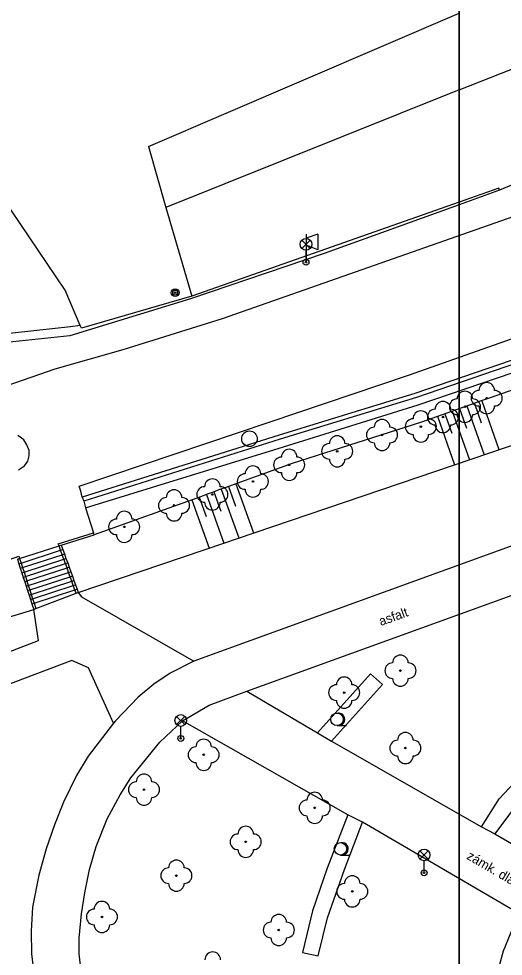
# Model space of a CAD drawing. Extents: x -493753 to -49290, y -1127285 to -112654.
# Drawn here: x -493153.3 to -493122.2, y -1126683.6 to -1126623.4 of the extents above; entities that cross this region are included whole.
import ezdxf

# ---------------------------------------------------------------- set-up
doc = ezdxf.new("R2010")
doc.units = 0
for name, color, linetype in [('Vrstva 10', 7, 'Continuous'), ('Vrstva 11', 7, 'Continuous'), ('Vrstva 14', 7, 'Continuous'), ('Vrstva 15', 7, 'Continuous'), ('Vrstva 21', 7, 'Continuous'), ('Vrstva 22', 7, 'Continuous'), ('Vrstva 23', 7, 'Continuous'), ('Vrstva 25', 7, 'Continuous'), ('Vrstva 27', 7, 'Continuous'), ('Vrstva 33', 7, 'Continuous'), ('Vrstva 36', 7, 'Continuous'), ('Vrstva 40', 7, 'Continuous'), ('Vrstva 60', 7, 'Continuous'), ('Vrstva 7', 7, 'Continuous'), ('Vrstva 8', 7, 'Continuous'), ('Vrstva 9', 7, 'Continuous')]:
    doc.layers.add(name, color=color, linetype=linetype)

msp = doc.modelspace()

# ---------------------------------------------------------------- linework, layer by layer
at = {"layer": 'Vrstva 10'}
for p, q in [((-493082.44, -1126643.04), (-493142.03, -1126664.63)), ((-493152.93, -1126650.43), (-493153.31, -1126650.14)), ((-493152.75, -1126650.75), (-493152.93, -1126650.43)), ((-493152.6, -1126651.1), (-493152.75, -1126650.75)), ((-493152.6, -1126651.46), (-493152.6, -1126651.1)), ((-493152.68, -1126651.8), (-493152.6, -1126651.46)), ((-493153.27, -1126652.35), (-493152.9, -1126652.09)), ((-493152.9, -1126652.09), (-493152.68, -1126651.8)), ((-493150.53, -1126657.19), (-493148.41, -1126656.53))]:
    msp.add_line(p, q, dxfattribs=at)
for points in [[(-493112.94, -1126633.09), (-493140.21, -1126642.65), (-493146.57, -1126644.64), (-493150.94, -1126645.89), (-493157.69, -1126648.21), (-493160.43, -1126649.13), (-493160.67, -1126649.21), (-493174.89, -1126654.03), (-493197.62, -1126661.66)], [(-493090.15, -1126633.48), (-493092.4, -1126634.08), (-493099.93, -1126637.44), (-493110.38, -1126641.71), (-493117.7, -1126644.26), (-493127.72, -1126647.7), (-493136.47, -1126650.38), (-493149.09, -1126654.35)], [(-493149.09, -1126654.35), (-493148.97, -1126654.78), (-493148.46, -1126656.39)], [(-493148.41, -1126656.53), (-493148.46, -1126656.39)], [(-493150.53, -1126657.19), (-493150.43, -1126657.47), (-493150.33, -1126657.75), (-493150.23, -1126658.04), (-493150.12, -1126658.32), (-493150.02, -1126658.6), (-493149.92, -1126658.89), (-493149.82, -1126659.17), (-493149.72, -1126659.45), (-493149.62, -1126659.73), (-493149.51, -1126660.01), (-493149.44, -1126660.22)], [(-493138.62, -1126666.56), (-493112.91, -1126657.25)], [(-493153.35, -1126658.08), (-493153.25, -1126658.39), (-493153.16, -1126658.67), (-493153.06, -1126658.96), (-493152.97, -1126659.25), (-493152.88, -1126659.53), (-493152.79, -1126659.82), (-493152.69, -1126660.1), (-493152.6, -1126660.39), (-493152.51, -1126660.67), (-493152.42, -1126660.96), (-493152.3, -1126661.31)], [(-493149.44, -1126660.22), (-493149.23, -1126660.5), (-493142.03, -1126664.63)], [(-493161.82, -1126667.07), (-493152, -1126663.31), (-493152.3, -1126661.31)], [(-493147.17, -1126668.61), (-493148.78, -1126665.07), (-493149.85, -1126664.59), (-493159.66, -1126668.3), (-493160.04, -1126668.71), (-493160.26, -1126669.2), (-493160.35, -1126669.68), (-493160.32, -1126670.13), (-493151.92, -1126688.64), (-493151.32, -1126688.27)], [(-493138.62, -1126666.56), (-493134.08, -1126669.23)], [(-493147.17, -1126668.61), (-493148.81, -1126670.73), (-493149.55, -1126671.97), (-493150.38, -1126673.68), (-493150.96, -1126675.13), (-493151.51, -1126676.67), (-493151.97, -1126678.38), (-493152.37, -1126680.43), (-493152.47, -1126681.97), (-493152.44, -1126683.41), (-493152.26, -1126684.82), (-493152.04, -1126685.92), (-493151.32, -1126688.27)], [(-493149.25, -1126684.51), (-493149.38, -1126683.42), (-493149.39, -1126682.42), (-493149.23, -1126680.86), (-493149.01, -1126679.5), (-493148.71, -1126678.01), (-493148.29, -1126676.52), (-493147.59, -1126674.75), (-493146.75, -1126673.21), (-493146.07, -1126672.12), (-493144.21, -1126669.84), (-493142.74, -1126668.47)], [(-493132.14, -1126674.49), (-493142.74, -1126668.47)], [(-493134.08, -1126669.23), (-493133.19, -1126669.76)], [(-493133.19, -1126669.76), (-493123.56, -1126675.27)], [(-493131.19, -1126674.97), (-493132.14, -1126674.49)], [(-493121.17, -1126680.84), (-493131.19, -1126674.97)], [(-493123.56, -1126675.27), (-493122.71, -1126675.72)], [(-493122.71, -1126675.72), (-493117.72, -1126678.6)]]:
    msp.add_lwpolyline(points, dxfattribs=at)
at = {"layer": 'Vrstva 11'}
msp.add_line((-493144.94, -1126631.6), (-493125, -1126623.04), dxfattribs=at)
for points in [[(-493125, -1126627.95), (-493116.83, -1126624.74)], [(-493125, -1126627.95), (-493143.81, -1126635.5)], [(-493149.18, -1126654.1), (-493149.28, -1126653.72), (-493149.38, -1126653.4), (-493137.19, -1126649.29), (-493128.18, -1126646.24), (-493118.42, -1126642.8), (-493110.87, -1126640.09), (-493100.4, -1126636.25), (-493092.65, -1126633.27), (-493092.49, -1126633.69)], [(-493092.49, -1126633.69), (-493099.98, -1126637.24), (-493110.5, -1126641.46), (-493117.77, -1126644.01), (-493127.83, -1126647.45), (-493136.55, -1126650.13), (-493149.18, -1126654.1), (-493149.09, -1126654.35)], [(-493153.35, -1126658.08), (-493153.21, -1126658.04), (-493150.67, -1126657.23), (-493150.53, -1126657.19)], [(-493153.25, -1126658.39), (-493153.11, -1126658.35), (-493150.57, -1126657.51), (-493150.43, -1126657.47)], [(-493153.16, -1126658.67), (-493153.02, -1126658.62), (-493150.47, -1126657.8), (-493150.33, -1126657.75)], [(-493153.06, -1126658.96), (-493152.92, -1126658.92), (-493150.36, -1126658.09), (-493150.23, -1126658.04)], [(-493152.97, -1126659.25), (-493152.83, -1126659.2), (-493150.26, -1126658.37), (-493150.12, -1126658.32)], [(-493152.88, -1126659.53), (-493152.74, -1126659.48), (-493150.16, -1126658.65), (-493150.02, -1126658.6)], [(-493152.79, -1126659.82), (-493152.65, -1126659.77), (-493150.06, -1126658.94), (-493149.92, -1126658.89)], [(-493152.69, -1126660.1), (-493152.55, -1126660.05), (-493149.96, -1126659.22), (-493149.82, -1126659.17)], [(-493152.6, -1126660.39), (-493152.46, -1126660.35), (-493149.86, -1126659.49), (-493149.72, -1126659.45)], [(-493152.51, -1126660.67), (-493152.37, -1126660.62), (-493149.76, -1126659.78), (-493149.62, -1126659.73)], [(-493152.42, -1126660.96), (-493152.27, -1126660.91), (-493149.66, -1126660.06), (-493149.51, -1126660.01)], [(-493152.3, -1126661.31), (-493152.16, -1126661.26), (-493149.58, -1126660.27), (-493149.44, -1126660.22)], [(-493142.03, -1126664.63), (-493143.55, -1126665.41), (-493144.58, -1126666.11), (-493145.6, -1126666.94), (-493147.06, -1126668.46), (-493147.17, -1126668.61)], [(-493142.74, -1126668.47), (-493141.03, -1126667.45), (-493138.62, -1126666.56)]]:
    msp.add_lwpolyline(points, dxfattribs=at)
at = {"layer": 'Vrstva 14'}
for points in [[(-493149.44, -1126660.22), (-493140.03, -1126657.04), (-493139.28, -1126656.77), (-493123.03, -1126651.26), (-493122.28, -1126650.99), (-493111.39, -1126647.34), (-493110.63, -1126647.08), (-493100.45, -1126643.64), (-493095.29, -1126641.22), (-493094.56, -1126640.89), (-493080.63, -1126634.46), (-493079.9, -1126634.13), (-493077.86, -1126633.18)], [(-493148.97, -1126654.78), (-493136.27, -1126650.87), (-493127.63, -1126648.17), (-493117.51, -1126644.74), (-493110.16, -1126642.18), (-493099.61, -1126637.87), (-493092.16, -1126634.52), (-493089.97, -1126633.86), (-493090.15, -1126633.48)], [(-493112.97, -1126644.2), (-493123, -1126647.73), (-493123.38, -1126647.86), (-493123.76, -1126647.99), (-493124.14, -1126648.13), (-493124.51, -1126648.26), (-493127.41, -1126649.28), (-493135.72, -1126651.95), (-493140.03, -1126653.51), (-493140.41, -1126653.64), (-493140.79, -1126653.78), (-493141.16, -1126653.91), (-493141.54, -1126654.05), (-493148.41, -1126656.53)], [(-493186.94, -1126669.58), (-493183.37, -1126670.76), (-493152.3, -1126661.31)]]:
    msp.add_lwpolyline(points, dxfattribs=at)
at = {"layer": 'Vrstva 15'}
for p, q in [((-493124.01, -1126648.08), (-493123.57, -1126649.34)), ((-493123.54, -1126647.92), (-493122.44, -1126651.05)), ((-493125.9, -1126648.75), (-493125.46, -1126649.99)), ((-493125.43, -1126648.58), (-493124.33, -1126651.7)), ((-493124.96, -1126648.42), (-493124.52, -1126649.67)), ((-493124.49, -1126648.25), (-493123.38, -1126651.38)), ((-493126.37, -1126648.91), (-493125.28, -1126652.02)), ((-493139.8, -1126653.42), (-493139.34, -1126654.68)), ((-493139.33, -1126653.25), (-493138.19, -1126656.4)), ((-493141.68, -1126654.1), (-493141.23, -1126655.35)), ((-493141.21, -1126653.93), (-493140.09, -1126657.06)), ((-493140.74, -1126653.76), (-493140.29, -1126655.01)), ((-493140.27, -1126653.59), (-493139.14, -1126656.72)), ((-493142.15, -1126654.27), (-493141.03, -1126657.37))]:
    msp.add_line(p, q, dxfattribs=at)
at = {"layer": 'Vrstva 21'}
for p, q in [((-493122.42, -1126673.46), (-493120.22, -1126671.1)), ((-493120.94, -1126673.37), (-493122.71, -1126675.72)), ((-493123.56, -1126675.27), (-493122.42, -1126673.46)), ((-493132.14, -1126674.49), (-493133.47, -1126677.92)), ((-493132.35, -1126678.01), (-493131.19, -1126674.97)), ((-493133.47, -1126677.92), (-493134.41, -1126680.65)), ((-493133.44, -1126681.1), (-493132.35, -1126678.01)), ((-493134.41, -1126680.65), (-493135.05, -1126683.34)), ((-493134.04, -1126683.55), (-493133.44, -1126681.1)), ((-493135.05, -1126683.34), (-493134.04, -1126683.55))]:
    msp.add_line(p, q, dxfattribs=at)
msp.add_lwpolyline([(-493122.1, -1126690.56), (-493123.14, -1126690.53), (-493123.05, -1126687.84), (-493122.66, -1126685.11), (-493122.14, -1126683.22), (-493121.17, -1126680.84)], dxfattribs=at)
at = {"layer": 'Vrstva 22'}
for centre in [(-493123.22, -1126647.75), (-493124.62, -1126648.3), (-493126.03, -1126648.96), (-493127.45, -1126649.57), (-493129.94, -1126650.11), (-493132.82, -1126651.16), (-493135.9, -1126652.03), (-493138.23, -1126653.1), (-493140.83, -1126653.93), (-493143.29, -1126654.63), (-493146.49, -1126656.01), (-493128.76, -1126665.24), (-493132.37, -1126666.65), (-493128.44, -1126670.21), (-493141.39, -1126670.64), (-493145.22, -1126672.88), (-493134.26, -1126674.05), (-493138.69, -1126676.23), (-493143.14, -1126678.4), (-493131.85, -1126679.41), (-493147.92, -1126681.05), (-493136.57, -1126681.89)]:
    msp.add_circle(centre, 0.05, dxfattribs=at)
for centre, start, end in [((-493123.22, -1126647.25), 360, 180), ((-493124.62, -1126647.8), 360, 180), ((-493123.72, -1126647.75), 90, 270), ((-493122.72, -1126647.75), 270, 90), ((-493126.03, -1126648.46), 360, 180), ((-493125.12, -1126648.3), 90, 270), ((-493124.12, -1126648.3), 270, 90), ((-493127.45, -1126649.07), 360, 180), ((-493126.53, -1126648.96), 90, 270), ((-493125.53, -1126648.96), 270, 90), ((-493123.22, -1126648.25), 180, 0), ((-493129.94, -1126649.61), 360, 180), ((-493127.95, -1126649.57), 90, 270), ((-493126.95, -1126649.57), 270, 90), ((-493124.62, -1126648.8), 180, 0), ((-493130.44, -1126650.11), 90, 270), ((-493129.44, -1126650.11), 270, 90), ((-493126.03, -1126649.46), 180, 0), ((-493132.82, -1126650.66), 360, 180), ((-493127.45, -1126650.07), 180, 0), ((-493135.9, -1126651.53), 360, 180), ((-493133.32, -1126651.16), 90, 270), ((-493132.32, -1126651.16), 270, 90), ((-493129.94, -1126650.61), 180, 0), ((-493136.4, -1126652.03), 90, 270), ((-493135.4, -1126652.03), 270, 90), ((-493132.82, -1126651.66), 180, 0), ((-493138.23, -1126652.6), 360, 180), ((-493140.83, -1126653.43), 360, 180), ((-493138.73, -1126653.1), 90, 270), ((-493137.73, -1126653.1), 270, 90), ((-493135.9, -1126652.53), 180, 0), ((-493141.33, -1126653.93), 90, 270), ((-493140.33, -1126653.93), 270, 90), ((-493143.79, -1126654.63), 90, 270), ((-493143.29, -1126654.13), 360, 180), ((-493142.79, -1126654.63), 270, 90), ((-493138.23, -1126653.6), 180, 0), ((-493140.83, -1126654.43), 180, 0), ((-493146.49, -1126655.51), 360, 180), ((-493143.29, -1126655.13), 180, 0), ((-493146.99, -1126656.01), 90, 270), ((-493145.99, -1126656.01), 270, 90), ((-493146.49, -1126656.51), 180, 0), ((-493128.76, -1126664.74), 0, 180), ((-493129.26, -1126665.24), 90, 270), ((-493128.26, -1126665.24), 270, 90), ((-493132.87, -1126666.65), 90, 270), ((-493132.37, -1126666.15), 0, 180), ((-493131.87, -1126666.65), 270, 90), ((-493128.76, -1126665.74), 180, 0), ((-493132.37, -1126667.15), 180, 0), ((-493128.44, -1126669.71), 0, 180), ((-493141.39, -1126670.14), 0, 180), ((-493128.94, -1126670.21), 90, 270), ((-493127.94, -1126670.21), 270, 90), ((-493141.89, -1126670.64), 90, 270), ((-493140.89, -1126670.64), 270, 90), ((-493128.44, -1126670.71), 180, 0), ((-493141.39, -1126671.14), 180, 0), ((-493145.22, -1126672.38), 0, 180), ((-493145.72, -1126672.88), 90, 270), ((-493144.72, -1126672.88), 270, 90), ((-493145.22, -1126673.38), 180, 0), ((-493134.26, -1126673.55), 0, 180), ((-493134.76, -1126674.05), 90, 270), ((-493133.76, -1126674.05), 270, 90), ((-493134.26, -1126674.55), 180, 0), ((-493138.69, -1126675.73), 0, 180), ((-493139.19, -1126676.23), 90, 270), ((-493138.19, -1126676.23), 270, 90), ((-493138.69, -1126676.73), 180, 0), ((-493143.14, -1126677.9), 0, 180), ((-493143.64, -1126678.4), 90, 270), ((-493142.64, -1126678.4), 270, 90), ((-493131.85, -1126678.91), 0, 180), ((-493143.14, -1126678.9), 180, 0), ((-493132.35, -1126679.41), 90, 270), ((-493131.35, -1126679.41), 270, 90), ((-493147.92, -1126680.55), 0, 180), ((-493131.85, -1126679.91), 180, 0), ((-493148.42, -1126681.05), 90, 270), ((-493147.42, -1126681.05), 270, 90), ((-493136.57, -1126681.39), 0, 180), ((-493147.92, -1126681.55), 180, 0), ((-493137.07, -1126681.89), 90, 270), ((-493136.07, -1126681.89), 270, 90), ((-493136.57, -1126682.39), 180, 0), ((-493140.81, -1126683.8), 0, 180)]:
    msp.add_arc(centre, 0.5, start, end, dxfattribs=at)
at = {"layer": 'Vrstva 23'}
for p, q in [((-493134.08, -1126669.23), (-493130.68, -1126665.44)), ((-493130.68, -1126665.44), (-493129.91, -1126666.14)), ((-493129.91, -1126666.14), (-493133.19, -1126669.76))]:
    msp.add_line(p, q, dxfattribs=at)
at = {"layer": 'Vrstva 25'}
for radius in [0.25, 0.158, 0.05]:
    msp.add_circle((-493143.22, -1126640.97), radius, dxfattribs=at)
at = {"layer": 'Vrstva 27'}
msp.add_circle((-493138.45, -1126650.351), 0.5, dxfattribs=at)
at = {"layer": 'Vrstva 33'}
for p, q in [((-493134.82, -1126637.22), (-493134.82, -1126638.97)), ((-493134.07, -1126637.22), (-493134.82, -1126637.47)), ((-493134.07, -1126637.22), (-493134.07, -1126638.22)), ((-493135.085, -1126637.605), (-493134.555, -1126638.135)), ((-493135.085, -1126638.135), (-493134.555, -1126637.605)), ((-493134.07, -1126638.22), (-493134.82, -1126637.92)), ((-493134.82, -1126639.02), (-493134.82, -1126638.245)), ((-493143.125, -1126668.175), (-493142.595, -1126668.705)), ((-493143.125, -1126668.705), (-493142.595, -1126668.175)), ((-493142.86, -1126669.59), (-493142.86, -1126668.815)), ((-493127.505, -1126676.805), (-493126.975, -1126677.335)), ((-493127.505, -1126677.335), (-493126.975, -1126676.805)), ((-493127.24, -1126678.22), (-493127.24, -1126677.445))]:
    msp.add_line(p, q, dxfattribs=at)
for centre, radius in [((-493134.82, -1126637.87), 0.375), ((-493134.82, -1126639.02), 0.19), ((-493134.82, -1126639.02), 0.05), ((-493142.86, -1126668.44), 0.375), ((-493142.86, -1126669.59), 0.19), ((-493142.86, -1126669.59), 0.05), ((-493127.24, -1126677.07), 0.375), ((-493127.24, -1126678.22), 0.19), ((-493127.24, -1126678.22), 0.05)]:
    msp.add_circle(centre, radius, dxfattribs=at)
at = {"layer": 'Vrstva 36'}
for p, q in [((-493132.83, -1126668.77), (-493132.73, -1126668.77)), ((-493132.73, -1126668.77), (-493132.23, -1126668.77)), ((-493132.61, -1126677.08), (-493132.51, -1126677.08)), ((-493132.51, -1126677.08), (-493132.01, -1126677.08))]:
    msp.add_line(p, q, dxfattribs=at)
for centre in [(-493132.83, -1126668.37), (-493132.61, -1126676.68)]:
    msp.add_circle(centre, 0.4, dxfattribs=at)
for centre in [(-493132.73, -1126668.37), (-493132.51, -1126676.68)]:
    msp.add_arc(centre, 0.4, 259.69515, 97.18076, dxfattribs=at)
at = {"layer": 'Vrstva 60'}
for points in [[(-493659.148, -1127000), (-493125, -1127000), (-493125, -1126587.478)], [(-493125, -1126587.478), (-493125, -1127000), (-492991.121, -1127000)]]:
    msp.add_lwpolyline(points, dxfattribs=at)
at = {"layer": 'Vrstva 7'}
msp.add_line((-493122.4, -1126634.39), (-493122.44, -1126634.27), dxfattribs=at)
for points in [[(-493149.32, -1126643.08), (-493150.27, -1126640.82), (-493154.93, -1126633.96), (-493155.18, -1126633.59), (-493161.73, -1126622.08), (-493166.5, -1126613.22), (-493164.27, -1126610.59), (-493151.62, -1126596.53)], [(-493144.94, -1126631.6), (-493143.81, -1126635.5), (-493142.15, -1126641.2)], [(-493122.44, -1126634.27), (-493125, -1126635.17)], [(-493122.4, -1126634.39), (-493125, -1126635.33)], [(-493125, -1126635.33), (-493133.66, -1126638.47), (-493142.24, -1126641.36), (-493149.99, -1126643.74), (-493158.54, -1126644.65)], [(-493125, -1126635.17), (-493142.15, -1126641.2)], [(-493142.15, -1126641.2), (-493149.24, -1126643.26), (-493149.32, -1126643.08)], [(-493149.32, -1126643.08), (-493149.93, -1126643.17), (-493158.19, -1126644.07), (-493158.87, -1126642.84)]]:
    msp.add_lwpolyline(points, dxfattribs=at)
at = {"layer": 'Vrstva 8'}
msp.add_lwpolyline([(-493120.08, -1126633.44), (-493122.4, -1126634.39)], dxfattribs=at)
at = {"layer": 'Vrstva 9'}
for points in [[(-493149.58, -1126660.27), (-493149.66, -1126660.06), (-493149.76, -1126659.78), (-493149.86, -1126659.49), (-493149.96, -1126659.22), (-493150.06, -1126658.94), (-493150.16, -1126658.65), (-493150.26, -1126658.37), (-493150.36, -1126658.09), (-493150.47, -1126657.8), (-493150.57, -1126657.51), (-493150.67, -1126657.23), (-493150.72, -1126657.09), (-493148.46, -1126656.39)], [(-493157.93, -1126659.57), (-493153.26, -1126657.89), (-493153.21, -1126658.04), (-493153.11, -1126658.35), (-493153.02, -1126658.62), (-493152.92, -1126658.92), (-493152.83, -1126659.2), (-493152.74, -1126659.48), (-493152.65, -1126659.77), (-493152.55, -1126660.05), (-493152.46, -1126660.35), (-493152.37, -1126660.62), (-493152.27, -1126660.91), (-493152.16, -1126661.26)]]:
    msp.add_lwpolyline(points, dxfattribs=at)

# ---------------------------------------------------------------- texts
at = {"layer": 'Vrstva 40'}
for s, rotation, p in [('asfalt', 19.90613, (-493130.014, -1126662.381)), ('zámk. dlažba', 329.63702, (-493124.561, -1126677.296))]:
    msp.add_text(s, height=0.6, rotation=rotation, dxfattribs=at).set_placement(p)

doc.saveas('drawing.dxf')
